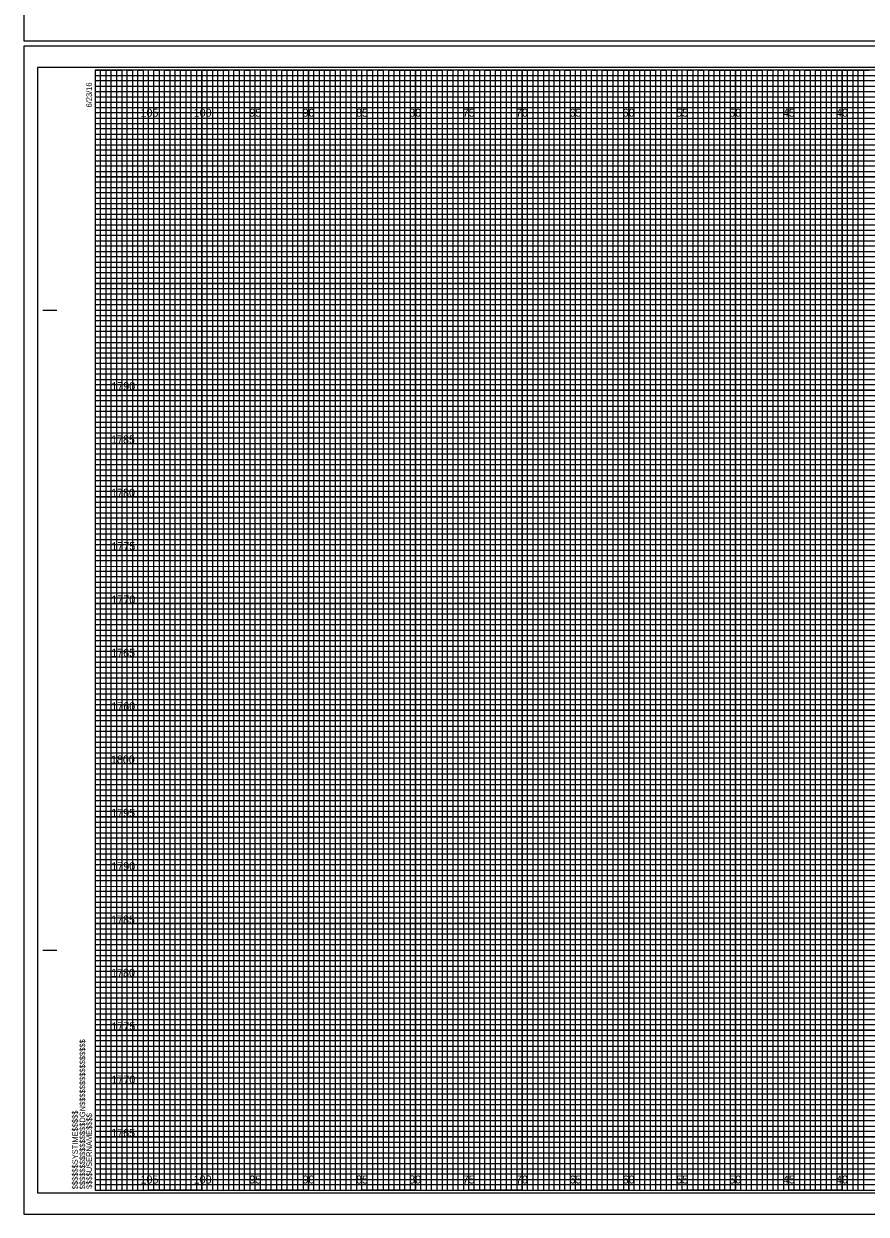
# Model space of a CAD drawing. Extents: x -7 to 392, y -2 to 440.
# Drawn here: x 223.6 to 302.5, y 111 to 222.5 of the extents above; entities that cross this region are included whole.
import ezdxf

# ---------------------------------------------------------------- set-up
doc = ezdxf.new("R2010")
doc.units = 0
for name, color, linetype in [('Prop Grid Mask', 7, 'Continuous'), ('Prop XS Elevation Labels', 7, 'Continuous'), ('Sheet Cross Section CELL', 7, 'Continuous'), ('Sheet Cross Section Grid Major CELL', 7, 'Continuous'), ('Sheet Cross Section Grid Middle CELL', 7, 'Continuous'), ('Sheet Cross Section Grid Minor 1 CELL', 7, 'Continuous'), ('Sheet Cross Section Grid Minor 2 CELL', 7, 'Continuous'), ('Sheet Cutting Line CELL', 7, 'Continuous'), ('Sheet DOT Grid CELL', 7, 'Continuous'), ('Sheet Plot Border Inside CELL', 7, 'Continuous'), ('Sheet Plot Border Outside CELL', 7, 'Continuous')]:
    doc.layers.add(name, color=color, linetype=linetype)

msp = doc.modelspace()

# ---------------------------------------------------------------- linework, layer by layer
at = {"layer": 'Sheet Cross Section CELL'}
for p, q in [((225.36, 195.71), (226.61, 195.71)), ((225.41, 195.71), (226.66, 195.71)), ((225.36, 135.71), (226.61, 135.71)), ((225.41, 135.71), (226.66, 135.71)), ((230.26, 113.21), (230.26, 113.21)), ((230.26, 113.21), (230.26, 113.21)), ((230.26, 113.21), (230.26, 113.21)), ((230.26, 113.21), (230.26, 113.21)), ((230.26, 113.21), (230.26, 113.21)), ((230.26, 113.21), (230.26, 113.21)), ((230.26, 113.21), (230.26, 113.21))]:
    msp.add_line(p, q, dxfattribs=at)
msp.add_lwpolyline([(390.26, 218.21), (230.26, 218.21), (230.26, 113.21), (390.26, 113.21)], close=True, dxfattribs=at)
at = {"layer": 'Sheet Cross Section Grid Major CELL'}
for p, q in [((235.26, 218.21), (230.26, 218.21)), ((235.26, 113.21), (235.26, 218.21)), ((245.26, 218.21), (240.26, 218.21)), ((240.26, 218.21), (240.26, 113.21)), ((245.26, 113.21), (245.26, 218.21)), ((255.26, 218.21), (250.26, 218.21)), ((250.26, 218.21), (250.26, 113.21)), ((255.26, 113.21), (255.26, 218.21)), ((265.26, 218.21), (260.26, 218.21)), ((260.26, 218.21), (260.26, 113.21)), ((265.26, 113.21), (265.26, 218.21)), ((275.26, 218.21), (270.26, 218.21)), ((270.26, 218.21), (270.26, 113.21)), ((275.26, 113.21), (275.26, 218.21)), ((285.26, 218.21), (280.26, 218.21)), ((280.26, 218.21), (280.26, 113.21)), ((285.26, 113.21), (285.26, 218.21)), ((295.26, 218.21), (290.26, 218.21)), ((290.26, 218.21), (290.26, 113.21)), ((295.26, 113.21), (295.26, 218.21)), ((305.26, 218.21), (300.26, 218.21)), ((300.26, 218.21), (300.26, 113.21)), ((240.26, 113.21), (235.26, 113.21)), ((250.26, 113.21), (245.26, 113.21)), ((260.26, 113.21), (255.26, 113.21)), ((270.26, 113.21), (265.26, 113.21)), ((280.26, 113.21), (275.26, 113.21)), ((290.26, 113.21), (285.26, 113.21)), ((300.26, 113.21), (295.26, 113.21))]:
    msp.add_line(p, q, dxfattribs=at)
for points in [[(230.26, 213.21), (390.26, 213.21), (390.26, 208.21), (230.26, 208.21)], [(230.26, 203.21), (390.26, 203.21), (390.26, 198.21), (230.26, 198.21)], [(230.26, 193.21), (390.26, 193.21), (390.26, 188.21), (230.26, 188.21)], [(230.26, 183.21), (390.26, 183.21), (390.26, 178.21), (230.26, 178.21)], [(230.26, 173.21), (390.26, 173.21), (390.26, 168.21), (230.26, 168.21)], [(230.26, 163.21), (390.26, 163.21), (390.26, 158.21), (230.26, 158.21)], [(230.26, 153.21), (390.26, 153.21), (390.26, 148.21), (230.26, 148.21)], [(230.26, 143.21), (390.26, 143.21), (390.26, 138.21), (230.26, 138.21)], [(230.26, 133.21), (390.26, 133.21), (390.26, 128.21), (230.26, 128.21)], [(230.26, 123.21), (390.26, 123.21), (390.26, 118.21), (230.26, 118.21)]]:
    msp.add_lwpolyline(points, dxfattribs=at)
at = {"layer": 'Sheet Cross Section Grid Middle CELL'}
for points in [[(230.26, 218.21), (232.76, 218.21), (232.76, 113.21), (237.76, 113.21), (237.76, 218.21), (242.76, 218.21), (242.76, 113.21), (247.76, 113.21), (247.76, 218.21), (252.76, 218.21), (252.76, 113.21), (257.76, 113.21), (257.76, 218.21), (262.76, 218.21), (262.76, 113.21), (267.76, 113.21), (267.76, 218.21), (272.76, 218.21), (272.76, 113.21), (277.76, 113.21), (277.76, 218.21), (282.76, 218.21), (282.76, 113.21), (287.76, 113.21), (287.76, 218.21), (292.76, 218.21), (292.76, 113.21), (297.76, 113.21), (297.76, 218.21), (302.76, 218.21)], [(230.26, 215.71), (367.76, 215.71)], [(230.26, 205.71), (390.26, 205.71), (390.26, 210.71), (230.26, 210.71)], [(230.26, 195.71), (390.26, 195.71), (390.26, 200.71), (230.26, 200.71)], [(230.26, 185.71), (390.26, 185.71), (390.26, 190.71), (230.26, 190.71)], [(230.26, 175.71), (390.26, 175.71), (390.26, 180.71), (230.26, 180.71)], [(230.26, 165.71), (390.26, 165.71), (390.26, 170.71), (230.26, 170.71)], [(230.26, 155.71), (390.26, 155.71), (390.26, 160.71), (230.26, 160.71)], [(230.26, 145.71), (390.26, 145.71), (390.26, 150.71), (230.26, 150.71)], [(230.26, 135.71), (390.26, 135.71), (390.26, 140.71), (230.26, 140.71)], [(230.26, 125.71), (390.26, 125.71), (390.26, 130.71), (230.26, 130.71)], [(230.26, 115.71), (390.26, 115.71), (390.26, 120.71), (230.26, 120.71)]]:
    msp.add_lwpolyline(points, dxfattribs=at)
at = {"layer": 'Sheet Cross Section Grid Minor 1 CELL'}
for p, q in [((230.26, 217.71), (360.26, 217.71)), ((360.26, 217.2), (230.26, 217.2)), ((230.26, 217.2), (230.26, 216.71)), ((230.26, 216.71), (360.26, 216.71)), ((360.26, 216.16), (230.26, 216.16)), ((230.26, 216.16), (230.26, 215.21)), ((230.26, 215.21), (390.26, 215.21))]:
    msp.add_line(p, q, dxfattribs=at)
for points in [[(230.26, 214.71), (365.26, 214.71), (390.26, 214.71), (390.26, 214.21), (230.26, 214.21)], [(230.26, 213.71), (390.26, 213.71), (390.26, 212.71), (230.26, 212.71)], [(230.26, 212.21), (390.26, 212.21), (390.26, 211.71), (230.26, 211.7)], [(230.26, 211.21), (390.26, 211.21), (390.26, 210.21), (230.26, 210.21)], [(230.26, 209.71), (390.26, 209.71), (390.26, 209.21), (230.26, 209.21)], [(230.26, 208.71), (390.26, 208.71), (390.26, 207.71), (230.26, 207.71)], [(230.26, 207.21), (390.26, 207.21), (390.26, 206.71), (230.26, 206.71)], [(230.26, 206.21), (390.26, 206.21), (390.26, 205.21), (230.26, 205.21)], [(230.26, 204.71), (390.26, 204.71), (390.26, 204.21), (230.26, 204.21)], [(230.26, 203.71), (390.26, 203.71), (390.26, 202.71), (230.26, 202.71)], [(230.26, 202.21), (390.26, 202.21), (390.26, 201.71), (230.26, 201.71)], [(230.26, 201.21), (390.26, 201.21), (390.26, 200.19), (390.26, 199.71), (390.26, 199.21), (230.26, 199.21)], [(230.26, 200.21), (390.26, 200.21), (390.26, 199.71), (230.26, 199.71)], [(230.26, 198.71), (390.26, 198.71), (390.26, 197.71), (230.26, 197.73)], [(230.26, 197.73), (390.26, 197.71), (390.26, 197.21), (230.26, 197.21)], [(230.26, 196.71), (390.26, 196.71), (390.26, 196.21), (230.26, 196.21)], [(230.26, 195.21), (390.26, 195.21), (390.26, 194.71), (230.26, 194.71)], [(230.26, 194.21), (390.26, 194.21), (390.26, 193.71), (230.26, 193.71)], [(230.23, 192.66), (390.26, 192.66), (390.26, 192.15), (230.23, 192.15)], [(230.26, 191.71), (390.26, 191.71), (390.26, 191.21), (230.26, 191.21)], [(230.26, 190.21), (390.26, 190.21), (390.26, 189.71), (230.26, 189.71)], [(230.26, 189.21), (390.26, 189.21), (390.26, 188.71), (230.26, 188.71)], [(230.26, 187.71), (390.26, 187.71), (390.26, 187.21), (230.26, 187.21)], [(230.26, 186.71), (390.26, 186.71), (390.26, 186.21), (230.26, 186.21)], [(230.26, 185.21), (390.26, 185.21), (390.26, 184.71), (230.26, 184.71)], [(230.26, 184.21), (390.26, 184.21), (390.26, 183.71), (230.26, 183.71)], [(230.26, 182.71), (390.26, 182.71), (390.26, 182.2), (230.26, 182.21)], [(230.26, 181.71), (390.26, 181.71), (390.26, 181.21), (230.26, 181.21)], [(230.26, 180.21), (390.26, 180.21), (390.26, 179.71), (230.26, 179.71)], [(230.26, 179.21), (390.26, 179.21), (390.26, 178.71), (230.26, 178.71)], [(230.26, 177.71), (390.26, 177.71), (390.26, 177.21), (230.26, 177.21)], [(230.26, 176.71), (390.26, 176.71), (390.26, 176.21), (230.26, 176.21)], [(230.26, 175.21), (390.26, 175.21), (390.26, 174.71), (230.26, 174.71)], [(230.26, 174.21), (390.26, 174.21), (390.26, 173.71), (230.26, 173.71)], [(230.26, 172.71), (390.26, 172.71), (390.26, 172.21), (230.26, 172.21)], [(230.26, 171.71), (390.3, 171.67), (390.26, 171.21), (230.26, 171.21)], [(230.26, 170.21), (390.26, 170.21), (390.26, 169.71), (230.26, 169.71)], [(230.26, 169.21), (390.26, 169.21), (390.26, 168.71), (230.26, 168.71)], [(230.26, 167.71), (390.26, 167.71), (390.26, 167.21), (230.26, 167.21)], [(230.26, 166.71), (390.26, 166.71), (390.26, 166.21), (230.26, 166.21)], [(230.26, 165.21), (390.26, 165.21), (390.26, 164.71), (230.26, 164.71)], [(230.26, 164.21), (390.26, 164.21), (390.26, 163.71), (230.26, 163.71)], [(230.26, 162.71), (390.26, 162.71), (390.26, 162.21), (230.26, 162.21)], [(230.26, 161.71), (390.26, 161.71), (390.26, 161.21), (230.26, 161.21)], [(230.26, 160.21), (390.26, 160.21), (390.26, 159.71), (230.26, 159.71)], [(230.26, 159.21), (390.26, 159.21), (390.26, 158.71), (230.26, 158.71)], [(230.26, 157.71), (390.26, 157.71), (390.26, 157.21), (230.26, 157.21)], [(230.26, 156.71), (390.26, 156.71), (390.26, 156.21), (230.26, 156.21)], [(230.26, 155.21), (390.26, 155.21), (390.26, 154.71), (230.26, 154.71)], [(230.26, 154.21), (390.26, 154.21), (390.26, 153.71), (230.26, 153.71)], [(230.26, 152.71), (390.26, 152.71), (390.26, 152.2), (230.26, 152.21)], [(230.26, 151.71), (390.26, 151.71), (390.26, 151.21), (230.26, 151.21)], [(230.26, 150.21), (390.26, 150.21), (390.26, 149.71), (230.26, 149.71)], [(230.26, 149.21), (390.26, 149.21), (390.26, 148.71), (230.26, 148.71)], [(230.26, 147.71), (390.26, 147.71), (390.26, 147.21), (230.26, 147.21)], [(230.26, 146.71), (390.26, 146.71), (390.26, 146.21), (230.26, 146.21)], [(230.26, 145.21), (390.26, 145.21), (390.26, 144.71), (230.26, 144.71)], [(230.26, 144.21), (390.26, 144.21), (390.26, 143.71), (230.26, 143.71)], [(230.26, 142.71), (390.26, 142.71), (390.26, 142.21), (230.26, 142.21)], [(230.26, 141.71), (390.3, 141.67), (390.26, 141.21), (230.26, 141.21)], [(230.26, 140.21), (390.26, 140.21), (390.26, 139.71), (230.26, 139.71)], [(230.26, 139.21), (390.26, 139.21), (390.26, 138.71), (230.26, 138.71)], [(230.26, 137.71), (390.26, 137.71), (390.26, 137.21), (230.26, 137.21)], [(230.26, 136.71), (390.26, 136.71), (390.26, 136.21), (230.26, 136.21)], [(230.26, 135.21), (390.26, 135.21), (390.26, 134.71), (230.26, 134.71)], [(230.26, 134.21), (390.26, 134.21), (390.26, 133.71), (230.26, 133.71)], [(230.26, 132.71), (390.26, 132.71), (390.26, 132.21), (230.26, 132.21)], [(230.26, 131.71), (390.26, 131.71), (390.26, 131.21), (230.26, 131.21)], [(230.26, 130.21), (390.26, 130.21), (390.26, 129.71), (230.26, 129.71)], [(230.26, 129.21), (390.26, 129.21), (390.26, 128.71), (230.26, 128.71)], [(230.26, 127.71), (390.26, 127.71), (390.26, 127.21), (230.26, 127.21)], [(230.26, 126.71), (390.26, 126.71), (390.26, 126.21), (230.26, 126.21)], [(230.26, 125.21), (390.26, 125.21), (390.26, 124.71), (230.26, 124.71)], [(230.26, 124.21), (390.26, 124.21), (390.26, 123.71), (230.26, 123.71)], [(230.26, 122.71), (390.26, 122.71), (390.26, 122.21), (230.26, 122.21)], [(230.26, 121.71), (390.26, 121.71), (390.26, 121.21), (230.26, 121.21)], [(230.26, 120.21), (390.26, 120.21), (390.26, 119.71), (230.26, 119.71)], [(230.26, 119.21), (390.26, 119.21), (390.26, 118.71), (230.26, 118.71)], [(230.26, 117.71), (390.26, 117.71), (390.26, 117.21), (230.26, 117.21)], [(230.26, 116.71), (390.26, 116.71), (390.26, 116.21), (230.26, 116.21)], [(230.26, 115.21), (390.26, 115.21), (390.26, 114.71), (230.26, 114.71)], [(230.26, 114.21), (390.26, 114.21), (390.26, 113.71), (230.26, 113.71)]]:
    msp.add_lwpolyline(points, dxfattribs=at)
at = {"layer": 'Sheet Cross Section Grid Minor 2 CELL'}
for points in [[(230.26, 113.21), (230.76, 113.21), (230.76, 218.21), (231.26, 218.21), (231.26, 113.21)], [(231.26, 113.21), (231.76, 113.21), (231.76, 218.21), (232.26, 218.21), (232.26, 113.21)], [(232.76, 113.21), (233.26, 113.21), (233.26, 218.21), (233.76, 218.21), (233.76, 113.21)], [(233.76, 113.21), (234.26, 113.21), (234.26, 218.21), (234.76, 218.21), (234.76, 113.21)], [(235.26, 113.21), (235.76, 113.21), (235.76, 218.21), (236.26, 218.21), (236.26, 113.21)], [(236.26, 113.21), (236.76, 113.21), (236.76, 218.21), (237.26, 218.21), (237.26, 113.21)], [(237.76, 113.21), (238.26, 113.21), (238.26, 218.21), (238.76, 218.21), (238.76, 113.21)], [(238.76, 113.21), (239.26, 113.21), (239.26, 218.21), (239.76, 218.21), (239.76, 113.21)], [(240.26, 113.21), (240.76, 113.21), (240.76, 218.21), (241.26, 218.21), (241.26, 113.21)], [(241.26, 113.21), (241.76, 113.21), (241.76, 218.21), (242.26, 218.21), (242.26, 113.21)], [(242.76, 113.21), (243.26, 113.21), (243.26, 218.21), (243.76, 218.21), (243.76, 113.21)], [(243.76, 113.21), (244.26, 113.21), (244.26, 218.21), (244.76, 218.21), (244.76, 113.21)], [(245.26, 113.21), (245.76, 113.21), (245.76, 218.21), (246.26, 218.21), (246.26, 113.21)], [(246.26, 113.21), (246.76, 113.21), (246.76, 218.21), (247.26, 218.21), (247.26, 113.21)], [(247.76, 113.21), (248.26, 113.21), (248.26, 218.21), (248.76, 218.21), (248.76, 113.21)], [(248.76, 113.21), (249.26, 113.21), (249.26, 218.21), (249.76, 218.21), (249.76, 113.21)], [(250.26, 113.21), (250.76, 113.21), (250.76, 218.21), (251.26, 218.21), (251.26, 113.21)], [(251.26, 113.21), (251.76, 113.21), (251.76, 218.21), (252.26, 218.21), (252.26, 113.21)], [(252.76, 113.21), (253.26, 113.21), (253.26, 218.21), (253.76, 218.21), (253.76, 113.21)], [(253.76, 113.21), (254.26, 113.21), (254.26, 218.21), (254.76, 218.21), (254.76, 113.21)], [(255.26, 113.21), (255.76, 113.21), (255.76, 218.21), (256.26, 218.21), (256.26, 113.21)], [(256.26, 113.21), (256.76, 113.21), (256.76, 218.21), (257.26, 218.21), (257.26, 113.21)], [(257.76, 113.21), (258.26, 113.21), (258.26, 218.21), (258.76, 218.21), (258.76, 113.21)], [(258.76, 113.21), (259.26, 113.21), (259.26, 218.21), (259.76, 218.21), (259.76, 113.21)], [(260.26, 113.21), (260.76, 113.21), (260.76, 218.21), (261.26, 218.21), (261.26, 113.21)], [(261.26, 113.21), (261.76, 113.21), (261.76, 218.21), (262.26, 218.21), (262.26, 113.21)], [(262.76, 113.21), (263.26, 113.21), (263.26, 218.21), (263.76, 218.21), (263.76, 113.21)], [(263.76, 113.21), (264.26, 113.21), (264.26, 218.21), (264.76, 218.21), (264.76, 113.21)], [(265.26, 113.21), (265.76, 113.21), (265.76, 218.21), (266.26, 218.21), (266.26, 113.21)], [(266.26, 113.21), (266.76, 113.21), (266.76, 218.21), (267.26, 218.21), (267.26, 113.21)], [(267.76, 113.21), (268.26, 113.21), (268.26, 218.21), (268.76, 218.21), (268.76, 113.21)], [(268.76, 113.21), (269.26, 113.21), (269.26, 218.21), (269.76, 218.21), (269.76, 113.21)], [(270.26, 113.21), (270.76, 113.21), (270.76, 218.21), (271.26, 218.21), (271.26, 113.21)], [(271.26, 113.21), (271.76, 113.21), (271.76, 218.21), (272.26, 218.21), (272.26, 113.21)], [(272.76, 113.21), (273.26, 113.21), (273.26, 218.21), (273.76, 218.21), (273.76, 113.21)], [(273.76, 113.21), (274.26, 113.21), (274.26, 218.21), (274.76, 218.21), (274.76, 113.21)], [(275.26, 113.21), (275.76, 113.21), (275.76, 218.21), (276.26, 218.21), (276.26, 113.21)], [(276.26, 113.21), (276.76, 113.21), (276.76, 218.21), (277.26, 218.21), (277.26, 113.21)], [(277.76, 113.21), (278.26, 113.21), (278.26, 218.21), (278.76, 218.21), (278.76, 113.21)], [(278.76, 113.21), (279.26, 113.21), (279.26, 218.21), (279.76, 218.21), (279.76, 113.21)], [(280.26, 113.21), (280.76, 113.21), (280.76, 218.21), (281.26, 218.21), (281.26, 113.21)], [(281.26, 113.21), (281.76, 113.21), (281.76, 218.21), (282.26, 218.21), (282.26, 113.21)], [(282.76, 113.21), (283.26, 113.21), (283.26, 218.21), (283.76, 218.21), (283.76, 113.21)], [(283.76, 113.21), (284.26, 113.21), (284.26, 218.21), (284.76, 218.21), (284.76, 113.21)], [(285.26, 113.21), (285.76, 113.21), (285.76, 218.21), (286.26, 218.21), (286.26, 113.21)], [(286.26, 113.21), (286.76, 113.21), (286.76, 218.21), (287.26, 218.21), (287.26, 113.21)], [(287.76, 113.21), (288.26, 113.21), (288.26, 218.21), (288.76, 218.21), (288.76, 113.21)], [(288.76, 113.21), (289.26, 113.21), (289.26, 218.21), (289.76, 218.21), (289.76, 113.21)], [(290.26, 113.21), (290.76, 113.21), (290.76, 218.21), (291.26, 218.21), (291.26, 113.21)], [(291.26, 113.21), (291.76, 113.21), (291.76, 218.21), (292.26, 218.21), (292.26, 113.21)], [(292.76, 113.21), (293.26, 113.21), (293.26, 218.21), (293.76, 218.21), (293.76, 113.21)], [(293.76, 113.21), (294.26, 113.21), (294.26, 218.21), (294.76, 218.21), (294.76, 113.21)], [(295.26, 113.21), (295.76, 113.21), (295.76, 218.21), (296.26, 218.21), (296.26, 113.21)], [(296.26, 113.21), (296.76, 113.21), (296.76, 218.21), (297.26, 218.21), (297.26, 113.21)], [(297.76, 113.21), (298.26, 113.21), (298.26, 218.21), (298.76, 218.21), (298.76, 113.21)], [(298.76, 113.21), (299.26, 113.21), (299.26, 218.21), (299.76, 218.21), (299.76, 113.21)], [(300.26, 113.21), (300.76, 113.21), (300.76, 218.21), (301.26, 218.21), (301.26, 113.21)], [(301.26, 113.21), (301.76, 113.21), (301.76, 218.21), (302.26, 218.21), (302.26, 113.21)]]:
    msp.add_lwpolyline(points, dxfattribs=at)
at = {"layer": 'Sheet Cutting Line CELL'}
for p, q in [((223.56, 330.46), (223.56, 220.96)), ((223.56, 220.96), (391.91, 220.96)), ((391.91, 220.46), (223.56, 220.46)), ((223.56, 220.46), (223.56, 110.96)), ((223.56, 110.96), (391.91, 110.96))]:
    msp.add_line(p, q, dxfattribs=at)
at = {"layer": 'Sheet DOT Grid CELL'}
for p, q in [((235.26, 113.21), (235.26, 218.21)), ((240.26, 113.21), (240.26, 218.21)), ((245.26, 113.21), (245.26, 218.21)), ((250.26, 113.21), (250.26, 218.21)), ((255.26, 113.21), (255.26, 218.21)), ((260.26, 113.21), (260.26, 218.21)), ((265.26, 113.21), (265.26, 218.21)), ((270.26, 113.21), (270.26, 218.21)), ((275.26, 113.21), (275.26, 218.21)), ((280.26, 113.21), (280.26, 218.21)), ((285.26, 113.21), (285.26, 218.21)), ((290.26, 113.21), (290.26, 218.21)), ((295.26, 113.21), (295.26, 218.21)), ((300.26, 113.21), (300.26, 218.21)), ((230.26, 213.21), (390.26, 213.21)), ((230.26, 208.21), (390.26, 208.21)), ((230.26, 203.21), (390.26, 203.21)), ((230.26, 198.21), (390.26, 198.21)), ((230.26, 193.21), (390.26, 193.21)), ((230.26, 188.21), (390.26, 188.21)), ((230.26, 183.21), (390.26, 183.21)), ((230.26, 178.21), (390.26, 178.21)), ((230.26, 173.21), (390.26, 173.21)), ((230.26, 168.21), (390.26, 168.21)), ((230.26, 163.21), (390.26, 163.21)), ((230.26, 158.21), (390.26, 158.21)), ((230.26, 153.21), (390.26, 153.21)), ((230.26, 148.21), (390.26, 148.21)), ((230.26, 143.21), (390.26, 143.21)), ((230.26, 138.21), (390.26, 138.21)), ((230.26, 133.21), (390.26, 133.21)), ((230.26, 128.21), (390.26, 128.21)), ((230.26, 123.21), (390.26, 123.21)), ((230.26, 118.21), (390.26, 118.21))]:
    msp.add_line(p, q, dxfattribs=at)
at = {"layer": 'Sheet Plot Border Inside CELL'}
msp.add_lwpolyline([(224.86, 112.96), (391.46, 112.96), (391.46, 218.46), (224.86, 218.46)], close=True, dxfattribs=at)
at = {"layer": 'Sheet Plot Border Outside CELL'}
for points in [[(223.56, 220.96), (391.91, 220.96), (391.91, 330.46), (223.56, 330.46)], [(223.56, 110.96), (391.91, 110.96), (391.91, 220.46), (223.56, 220.46)]]:
    msp.add_lwpolyline(points, close=True, dxfattribs=at)

# ---------------------------------------------------------------- texts
at = {"layer": 'Prop Grid Mask'}
for s, p in [('105', (234.5, 213.84)), ('100', (239.49, 213.84)), ('95', (244.71, 213.84)), ('90', (249.69, 213.84)), ('85', (254.71, 213.84)), ('80', (259.69, 213.84)), ('75', (264.71, 213.84)), ('70', (269.69, 213.84)), ('65', (274.71, 213.84)), ('60', (279.69, 213.84)), ('55', (284.71, 213.84)), ('50', (289.69, 213.84)), ('45', (294.71, 213.84)), ('40', (299.69, 213.84)), ('105', (234.5, 113.84)), ('100', (239.49, 113.84)), ('95', (244.71, 113.84)), ('90', (249.69, 113.84)), ('85', (254.71, 113.84)), ('80', (259.69, 113.84)), ('75', (264.71, 113.84)), ('70', (269.69, 113.84)), ('65', (274.71, 113.84)), ('60', (279.69, 113.84)), ('55', (284.71, 113.84)), ('50', (289.69, 113.84)), ('45', (294.71, 113.84)), ('40', (299.69, 113.84))]:
    msp.add_text(s, height=0.75, dxfattribs=at).set_placement(p)
at = {"layer": 'Prop XS Elevation Labels'}
for s, p in [('1790', (231.77, 188.21)), ('1785', (231.75, 183.21)), ('1780', (231.75, 178.21)), ('1775', (231.78, 173.21)), ('1770', (231.78, 168.21)), ('1765', (231.76, 163.21)), ('1760', (231.77, 158.21)), ('1800', (231.73, 153.21)), ('1795', (231.76, 148.21)), ('1790', (231.77, 143.21)), ('1785', (231.75, 138.21)), ('1780', (231.75, 133.21)), ('1775', (231.78, 128.21)), ('1770', (231.78, 123.21)), ('1765', (231.76, 118.21))]:
    msp.add_text(s, height=0.75, dxfattribs=at).set_placement(p)
at = {"layer": 'Sheet Cross Section CELL'}
for s, p in [('6/23/16', (229.94, 214.71)), ('$$$$$$$$$$$$$$$$DGN$$$$$$$$$$$$$$$$', (229.32, 113.3)), ('$$$$$$SYSTIME$$$$$', (228.63, 113.3)), ('$$$$USERNAME$$$$', (229.95, 113.33))]:
    msp.add_text(s, height=0.525, rotation=90, dxfattribs=at).set_placement(p)

doc.saveas('drawing.dxf')
